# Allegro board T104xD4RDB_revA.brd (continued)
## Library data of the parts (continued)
C892 = CAP: signal model: DEFAULT_CAPACITOR_22.000000pF_2_1
C943 C966 = CAP: signal model: DEFAULT_CAPACITOR_560.000000pF_2_1
C967 = CAP: signal model: DEFAULT_CAPACITOR_620.000000pF_2_1
C991 = CAP: signal model: DEFAULT_CAPACITOR_680.000000pF_2_1
C1043 = CAP_E: signal model: DEFAULT_CAPACITOR_3.3e+08pF_2_1
C1138 = CAP
D1 D4-D6 = LED
D2 D3 = DIODE
D7 = DIODE_SCHOTTKY
F1-F5 = PTC
FB1-FB18 FB20-FB26 FB37-FB46 = BEAD
J1 = DDR4_DIMM
J2 = CONN_1X3
J3 = SD_CONN
J4 = CONN_2X8
J5 = USB_A_2
J6-J8 = JMP2
J9 = DSD9M
J10 = BAT_SOCKET
J11 = CONN_2X20
J12 = HDMI_CONN
J13 = FPC_20PIN
J14 J15 J18 J38 J39 = CONN_1X2
J16 J17 J32-J36 = CONN_3PIN
J19 = RJ45_LED_2X1
J20 J40 J41 = RJ45_LED
J21 = RJ45_LED_8
J26 = PCIE_X1
J27 J28 = MINIPCIE_CONN
J29 = SATA_CONN
J30 = CONN_2X35
J31 = CONN_2X5
J37 = ATX_PWR_CONN_20PIN
J42 = CONN_1X5
L1 L2 L19-L22 = IND_CM
L3 = IND: signal model: DEFAULT_INDUCTOR_2200nH_2_1
L4 L13 L15 = IND_IRON: signal model: DEFAULT_INDUCTOR_2200nH_2_1
L5 L12 L17 L18 = IND_IRON: signal model: DEFAULT_INDUCTOR_4700nH_2_1
L6 = IND_IRON: signal model: DEFAULT_INDUCTOR_220000nH_2_1
L7 = IND_IRON: signal model: DEFAULT_INDUCTOR_100000nH_2_1
L9 = IND_IRON: signal model: DEFAULT_INDUCTOR_215.000000nH_2_1
L10 L11 = IND_IRON: signal model: DEFAULT_INDUCTOR_3300nH_2_1
M2-M5 Z17 Z18 = MH
Q2-Q6 Q8 Q12-Q14 Q16-Q22 Q24-Q26 Q28 Q31 = NMOS
Q7 Q9-Q11 Q15 Q30 = NMOS_SO8FL
Q23 = PMOS_SO8
Q27 = PMOS
Q29 = TRANS_NPN
R1 = RES: tolerance: 1%; signal model: DEFAULT_RESISTOR_162.000000OHM_2_1
R2 R161 R503 R505 R509 R513 R516 R636 R640 = RES: tolerance: 1%; signal model: DEFAULT_RESISTOR_1000.000000OHM_2_1
R3 = RES: tolerance: 5%; signal model: DEFAULT_RESISTOR_162.000000OHM_2_1
R4-R7 R9-R11 R13 R17 R19 R21 R23 R25 R27 R29 R31 R33-R47 R53-R57 R69-R75 R78-R82 R85-R99 R101 R102 R123 R124 R132 R135-R137 R142-R144 R147 R148 R185 R204 R228-R235 R252 R259 R260 R262-R264 R269 R270 R272 R273 R276-R279 R282 R293-R297 R299-R301 R304-R306 R310 R311 R314-R321 R325 R330 R379-R385 R387-R393 R396-R399 R442 R443 R454 R496 R500 R501 R570 R698 R705 R706 R727-R729 R731 R732 R735-R738 R740 R749-R751 R753 R754 R757-R760 R763 = RES: tolerance: 5%; signal model: DEFAULT_RESISTOR_4700OHM_2_1
R8 R596 = RES: tolerance: 5%; signal model: DEFAULT_RESISTOR_20000OHM_2_1
R12 R59 R100 R108 R115-R122 R125-R130 R468 R486 R490 R549 R553 R555 R631 R694 = RES: tolerance: 5%; signal model: DEFAULT_RESISTOR_10.000000OHM_2_1
R14-R16 R18 R20 R22 R24 R26 R28 R30 R32 R58 R209 R211 R214-R217 R238 R239 R242-R246 R254 R255 R283 R448 R449 R492 R495 R511 = RES: tolerance: 5%; signal model: DEFAULT_RESISTOR_33.000000OHM_2_1
R48 R83 R84 R138 R162 R174 R176 R302 R323 R488 R494 R507 R518 R533 R540 R568 R652-R654 R656 R661 R665 R666 R670 R672 R673 R677 R681-R683 R687 R692 R695 R696 R718 R719 R722 = RES: tolerance: 5%; signal model: DEFAULT_RESISTOR_1000.000000OHM_2_1
R49-R52 R61 R151 R157 R170 R180 R182-R184 R190 R193 R221 R222 R226 R250 R251 R281 R312 R329 R489 R514 R515 R522 R525 R532 R552 R554 R572 R579 R588 R589 R607 R608 R625 R657 R659 R675 R676 R686 R688 R689 R700 R710-R717 R739 R741 R745 R761 R762 R767-R775 = RES: tolerance: 5%; signal model: DEFAULT_RESISTOR_0.001OHM_2_1
R60 R62-R68 R106 R107 R109-R112 R149 R150 R155 R156 R171 R456-R458 R462 R497 R498 R504 R506 R508 R539 R583 R585 R587 R601 R604-R606 R615 R618 R623 R642 R645 R648 R650 R658 R660 R662-R664 R667 R669 R671 R678 R679 R684 R685 R690 R691 R693 R703 R704 R721 R723 = RES: tolerance: 5%; signal model: DEFAULT_RESISTOR_10000OHM_2_1
R103 R133 R186 R187 R218 R219 R247 R248 R274 R275 R289 R290 R339 R341 R342 R352-R354 R363-R366 R375-R378 R394 R395 R470-R472 R699 R702 R733 R734 R755 R756 = RES: tolerance: 5%; signal model: DEFAULT_RESISTOR_510.000000OHM_2_1
R104 R105 R140 = RES: tolerance: 5%; signal model: DEFAULT_RESISTOR_698.000000OHM_2_1
R113 R114 R158 R159 R502 R558 R564 R577 R593 R599 R600 R602 R603 R613 R619 R627 R646 R651 = RES: tolerance: 1%; signal model: DEFAULT_RESISTOR_10000OHM_2_1
R131 = RES: tolerance: 5%; signal model: DEFAULT_RESISTOR_1500OHM_2_1
R134 = RES: tolerance: 5%; signal model: DEFAULT_RESISTOR_270.000000OHM_2_1
R139 = RES: tolerance: 5%; signal model: DEFAULT_RESISTOR_200.000000OHM_2_1
R145 = RES: tolerance: 1%; signal model: DEFAULT_RESISTOR_200.000000OHM_2_1
R146 = RES: tolerance: 1%; signal model: DEFAULT_RESISTOR_698.000000OHM_2_1
R152 R153 R641 R697 = RES: tolerance: 5%; signal model: DEFAULT_RESISTOR_100000OHM_2_1
R154 = RES: tolerance: 1%; signal model: DEFAULT_RESISTOR_51100OHM_2_1
R160 R167-R169 R520 R521 R536 R537 R701 = RES: tolerance: 1%; signal model: DEFAULT_RESISTOR_0.001OHM_2_1
R163 R164 = RES: tolerance: 5%; signal model: DEFAULT_RESISTOR_51100OHM_2_1
R165 = RES: tolerance: 5%; signal model: DEFAULT_RESISTOR_18200OHM_2_1
R166 = RES: tolerance: 1%; signal model: DEFAULT_RESISTOR_18200OHM_2_1
R172 R173 R519 R523 R524 R528 R538 = RES: tolerance: 5%; signal model: DEFAULT_RESISTOR_49.900000OHM_2_1
R175 R213 R517 = RES: tolerance: 1%; signal model: DEFAULT_RESISTOR_33.000000OHM_2_1
R177 R179 = RES: tolerance: 5%; signal model: DEFAULT_RESISTOR_330.000000OHM_2_1
R178 = RES: tolerance: 1%; signal model: DEFAULT_RESISTOR_330.000000OHM_2_1
R181 R188 R191 R194 R195 = RES: tolerance: 5%; signal model: DEFAULT_RESISTOR_5.100000OHM_2_1
R189 R192 = RES: tolerance: 5%; signal model: DEFAULT_RESISTOR_0.33OHM_2_1
R196-R203 R205 R206 R220 R249 R280 R292 R313 R386 R455 R551 R556 R655 R668 R674 R680 R707 R720 = RES: tolerance: 5%; signal model: DEFAULT_RESISTOR_100.000000OHM_2_1
R207 R208 R210 R236 R237 R240 R241 R265-R267 R271 R307-R309 R331 R333-R337 R344-R348 R350 R355-R362 R367-R374 R724-R726 R730 R746-R748 R752 = RES: tolerance: 5%; signal model: DEFAULT_RESISTOR_75.000000OHM_2_1
R212 R338 R349 R595 = RES: tolerance: 1%; signal model: DEFAULT_RESISTOR_75.000000OHM_2_1
R223 R225 = RES: tolerance: 5%; signal model: DEFAULT_RESISTOR_49900OHM_2_1
R224 R253 R284 R326 R742 R764 = RES: tolerance: 5%; signal model: DEFAULT_RESISTOR_15.000000OHM_2_1
R227 R256 R285 = RES: tolerance: 5%; signal model: DEFAULT_RESISTOR_2490OHM_2_1
R258 = RES: signal model: DEFAULT_RESISTOR_4700OHM_2_1
R268 R499 R574 = RES: tolerance: 1%; signal model: DEFAULT_RESISTOR_4700OHM_2_1
R286 = RES: tolerance: 5%; signal model: DEFAULT_RESISTOR_12100OHM_2_1
R288 = RES: signal model: DEFAULT_RESISTOR_33.000000OHM_2_1
R298 R327 R609 R743 R765 = RES: tolerance: 1%; signal model: DEFAULT_RESISTOR_2490OHM_2_1
R303 R324 = RES: tolerance: 5%; signal model: DEFAULT_RESISTOR_2000OHM_2_1
R328 R744 R766 = RES: tolerance: 1%; signal model: DEFAULT_RESISTOR_12100OHM_2_1
R340 R351 = RES: tolerance: 1%; signal model: DEFAULT_RESISTOR_510.000000OHM_2_1
R444 R452 R459 R461 = RES: tolerance: 5%; signal model: DEFAULT_RESISTOR_3010OHM_2_1
R445-R447 R450 R453 = RES: tolerance: 5%; signal model: DEFAULT_RESISTOR_51.000000OHM_2_1
R451 R464 R465 R480 R481 = RES: tolerance: 5%; signal model: DEFAULT_RESISTOR_200000OHM_2_1
R460 R463 R473-R479 = RES: tolerance: 5%; signal model: DEFAULT_RESISTOR_402000OHM_2_1
R466 R467 = RES: tolerance: 5%; signal model: DEFAULT_RESISTOR_47500OHM_2_1
R469 = RES: tolerance: 5%; signal model: DEFAULT_RESISTOR_75000OHM_2_1
R482-R485 = RES: tolerance: 5%; signal model: DEFAULT_RESISTOR_1800OHM_2_1
R487 R493 = RES: tolerance: 5%; signal model: DEFAULT_RESISTOR_13000OHM_2_1
R491 = RES: tolerance: 5%; signal model: DEFAULT_RESISTOR_0.02OHM_2_1
R512 R527 R535 = RES: tolerance: 1%; signal model: DEFAULT_RESISTOR_49.900000OHM_2_1
R534 = RES_PWR: signal model: DEFAULT_RESISTOR_49.900000OHM_2_1
R541-R545 R548 R708 R709 = RES: tolerance: 5%; signal model: DEFAULT_RESISTOR_150.000000OHM_2_1
R546 R547 = RES: tolerance: 1%; signal model: DEFAULT_RESISTOR_150.000000OHM_2_1
R550 = RES: tolerance: 1%; signal model: DEFAULT_RESISTOR_10.000000OHM_2_1
R565 R581 R590 = RES: tolerance: 5%; signal model: DEFAULT_RESISTOR_301.000000OHM_2_1
R566 R582 R591 = RES: tolerance: 1%; signal model: DEFAULT_RESISTOR_301.000000OHM_2_1
R567 R592 = RES: tolerance: 1%; signal model: DEFAULT_RESISTOR_1.000000OHM_2_1
R575 R610 = RES: tolerance: 1%; signal model: DEFAULT_RESISTOR_1780OHM_2_1
R576 R580 = RES: tolerance: 1%; signal model: DEFAULT_RESISTOR_2870OHM_2_1
R578 = RES: tolerance: 1%; signal model: DEFAULT_RESISTOR_3400OHM_2_1
R584 = RES: tolerance: 1%; signal model: DEFAULT_RESISTOR_2430OHM_2_1
R586 = RES: tolerance: 1%; signal model: DEFAULT_RESISTOR_3570OHM_2_1
R594 = RES: tolerance: 1%; signal model: DEFAULT_RESISTOR_7500OHM_2_1
R597 = RES: tolerance: 1%; signal model: DEFAULT_RESISTOR_49900OHM_2_1
R598 = RES: tolerance: 5%; signal model: DEFAULT_RESISTOR_46400OHM_2_1
R611 = RES: tolerance: 1%; signal model: DEFAULT_RESISTOR_124000OHM_2_1
R616 = RES: tolerance: 1%; signal model: DEFAULT_RESISTOR_1650OHM_2_1
R643 R649 = RES: tolerance: 1%; signal model: DEFAULT_RESISTOR_4320OHM_2_1
R644 = RES: tolerance: 1%; signal model: DEFAULT_RESISTOR_39200OHM_2_1
R647 = RES: tolerance: 1%; signal model: DEFAULT_RESISTOR_36500OHM_2_1
SW1-SW3 = SWITCH_DIP_8
SW4 SW5 = SWITCH_2P2
T1-T3 T12 T13 = H5007
T4-T11 = GST5009LF
TP1-TP19 = TP
U1 = T1040
U2 = 74LVC16373
U3 = FLASH-NOR-64Mx16
U4 = FLASH-NAND-BGA
U5-U7 = 74LVC1G86
U8 = FLASH-SERIAL-SO16
U9 = FLASH-SERIAL-SON
U10 U11 = RClamp0524J
U12 = PCA9546A
U13 = FXLP34P5X
U16-U18 = PI3PCIE3212
U19 = MAX1558H
U20 = SRV05-4
U21-U24 U26-U28 = 74CBTLV3253
U25 = 74LVC125
U29 U30 = MAX3232
U31 = DS1339U
U32 = EEPROM-I2C
U33 = LCDA15C-8
U34 = ADT7461
U35 = CH7301C
U36 = CM2020
U37 = DS90C387R
U38 = NKE0505SC_SIP_4P
U39 = 74CBTLV3257
U40 = ISO1176_SO16
U41 U78 = 74LVC1G14
U42 U45 = RTL8211E-VB
U48 U82 U83 = RTL8211DN
U51 U52 = VSC8514
U57 = EPM570F256
U58 = ICS843004-01
U60 U64-U69 = IR3475
U61 = 74CBTLV1G125
U62 = INA220
U72 = TPS51200
U73 U75 = MIC47100-MSOP8
U74 = TPS73701_SOT223
U76 = MAX811S
U77 = 74LVC2G74
U79 = IDT9FGV0641
U80 U81 = 74LVC1G66
X1-X4 = OSC
Y1 = CRYSTAL_32K
Y2-Y4 Y7-Y10 = CRYSTAL_4PIN
Z1-Z8 = FIDUCIAL
Z9-Z16 = MH_M8

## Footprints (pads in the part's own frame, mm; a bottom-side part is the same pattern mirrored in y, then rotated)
0201
  rect 0.32x0.3 smd: 1(-0.27,0) 2(0.27,0)
0402
  rect 0.55x0.5 smd: 1(-0.483,0) 2(0.483,0)
0402O
  custom 0.138x0.138 smd: 1(-0.5,0) 2(0.5,0)
0603
  rect 0.85x0.85 smd: 1(-0.762,0) 2(0.762,0)
0805
  rect 0.95x1.3 smd: 1(-0.965,0) 2(0.965,0)
0806
  rect 0.95x1.7 smd: 1(-0.965,0) 2(0.965,0)
1206
  rect 1.25x1.6 smd: 1(-1.524,0) 2(1.524,0)
7343
  rect 2.4x2.9 smd: 1(-3.05,0) 2(3.05,0)
BGA_P080_780
  round 0.35 smd: A2(-10,10.8) A3(-9.2,10.8) A4(-8.4,10.8) A5(-7.6,10.8) A6(-6.8,10.8) A7(-6,10.8) A8(-5.2,10.8) A9(-4.4,10.8) A10(-3.6,10.8) A11(-2.8,10.8) A12(-2,10.8) A13(-1.2,10.8) A14(-0.4,10.8) A15(0.4,10.8) A16(1.2,10.8) A17(2,10.8) A18(2.8,10.8) A19(3.6,10.8) A20(4.4,10.8) A21(5.2,10.8) A22(6,10.8) A23(6.8,10.8) A24(7.6,10.8) A25(8.4,10.8) A26(9.2,10.8) A27(10,10.8) AA1(-10.8,-5.2) AA2(-10,-5.2) AA3(-9.2,-5.2) AA4(-8.4,-5.2) AA5(-7.6,-5.2) AA6(-6.8,-5.2) AA7(-6,-5.2) AA8(-5.2,-5.2) AA9(-4.4,-5.2) AA10(-3.6,-5.2) AA11(-2.8,-5.2) AA12(-2,-5.2) AA13(-1.2,-5.2) AA14(-0.4,-5.2) AA15(0.4,-5.2) AA16(1.2,-5.2) AA17(2,-5.2) AA18(2.8,-5.2) AA19(3.6,-5.2) AA20(4.4,-5.2) AA21(5.2,-5.2) AA22(6,-5.2) AA23(6.8,-5.2) AA24(7.6,-5.2) AA25(8.4,-5.2) AA26(9.2,-5.2) AA27(10,-5.2) AA28(10.8,-5.2) AB1(-10.8,-6) AB2(-10,-6) AB3(-9.2,-6) AB4(-8.4,-6) AB5(-7.6,-6) AB6(-6.8,-6) AB7(-6,-6) AB8(-5.2,-6) AB9(-4.4,-6) AB10(-3.6,-6) AB11(-2.8,-6) AB12(-2,-6) AB13(-1.2,-6) AB14(-0.4,-6) AB15(0.4,-6) AB16(1.2,-6) AB17(2,-6) AB18(2.8,-6) AB19(3.6,-6) AB20(4.4,-6) AB21(5.2,-6) AB22(6,-6) AB23(6.8,-6) AB24(7.6,-6) AB25(8.4,-6) AB26(9.2,-6) AB27(10,-6) AB28(10.8,-6) AC1(-10.8,-6.8) AC2(-10,-6.8) AC3(-9.2,-6.8) AC4(-8.4,-6.8) AC5(-7.6,-6.8) AC6(-6.8,-6.8) AC7(-6,-6.8) AC8(-5.2,-6.8) AC9(-4.4,-6.8) AC10(-3.6,-6.8) AC11(-2.8,-6.8) AC12(-2,-6.8) AC13(-1.2,-6.8) AC14(-0.4,-6.8) AC15(0.4,-6.8) AC16(1.2,-6.8) AC17(2,-6.8) AC18(2.8,-6.8) AC19(3.6,-6.8) AC20(4.4,-6.8) AC21(5.2,-6.8) AC22(6,-6.8) AC23(6.8,-6.8) AC24(7.6,-6.8) AC25(8.4,-6.8) AC26(9.2,-6.8) AC27(10,-6.8) AC28(10.8,-6.8) AD1(-10.8,-7.6) AD2(-10,-7.6) AD3(-9.2,-7.6) AD4(-8.4,-7.6) AD5(-7.6,-7.6) AD6(-6.8,-7.6) AD7(-6,-7.6) AD8(-5.2,-7.6) AD9(-4.4,-7.6) AD10(-3.6,-7.6) AD11(-2.8,-7.6) AD12(-2,-7.6) AD13(-1.2,-7.6) AD14(-0.4,-7.6) AD15(0.4,-7.6) AD16(1.2,-7.6) AD17(2,-7.6) AD18(2.8,-7.6) AD19(3.6,-7.6) AD20(4.4,-7.6) AD21(5.2,-7.6) AD22(6,-7.6) AD23(6.8,-7.6) AD24(7.6,-7.6) AD25(8.4,-7.6) AD26(9.2,-7.6) AD27(10,-7.6) AD28(10.8,-7.6) AE1(-10.8,-8.4) AE2(-10,-8.4) AE3(-9.2,-8.4) AE4(-8.4,-8.4) AE5(-7.6,-8.4) AE6(-6.8,-8.4) AE7(-6,-8.4) AE8(-5.2,-8.4) AE9(-4.4,-8.4) AE10(-3.6,-8.4) AE11(-2.8,-8.4) AE12(-2,-8.4) AE13(-1.2,-8.4) AE14(-0.4,-8.4) AE15(0.4,-8.4) AE16(1.2,-8.4) AE17(2,-8.4) AE18(2.8,-8.4) AE19(3.6,-8.4) AE20(4.4,-8.4) AE21(5.2,-8.4) AE22(6,-8.4) AE23(6.8,-8.4) AE24(7.6,-8.4) AE25(8.4,-8.4) AE26(9.2,-8.4) AE27(10,-8.4) AE28(10.8,-8.4) AF1(-10.8,-9.2) AF2(-10,-9.2) AF3(-9.2,-9.2) AF4(-8.4,-9.2) AF5(-7.6,-9.2) AF6(-6.8,-9.2) AF7(-6,-9.2) AF8(-5.2,-9.2) AF9(-4.4,-9.2) AF10(-3.6,-9.2) AF11(-2.8,-9.2) AF12(-2,-9.2) AF13(-1.2,-9.2) AF14(-0.4,-9.2) AF15(0.4,-9.2) AF16(1.2,-9.2) AF17(2,-9.2) AF18(2.8,-9.2) AF19(3.6,-9.2) AF20(4.4,-9.2) AF21(5.2,-9.2) AF22(6,-9.2) AF23(6.8,-9.2) AF24(7.6,-9.2) AF25(8.4,-9.2) AF26(9.2,-9.2) AF27(10,-9.2) AF28(10.8,-9.2) AG1(-10.8,-10) AG2(-10,-10) AG3(-9.2,-10) AG4(-8.4,-10) AG5(-7.6,-10) AG6(-6.8,-10) AG7(-6,-10) AG8(-5.2,-10) AG9(-4.4,-10) AG10(-3.6,-10) AG11(-2.8,-10) AG12(-2,-10) AG13(-1.2,-10) AG14(-0.4,-10) AG15(0.4,-10) AG16(1.2,-10) AG17(2,-10) AG18(2.8,-10) AG19(3.6,-10) AG20(4.4,-10) AG21(5.2,-10) AG22(6,-10) AG23(6.8,-10) AG24(7.6,-10) AG25(8.4,-10) AG26(9.2,-10) AG27(10,-10) AG28(10.8,-10) AH2(-10,-10.8) AH3(-9.2,-10.8) AH4(-8.4,-10.8) AH5(-7.6,-10.8) AH6(-6.8,-10.8) AH7(-6,-10.8) AH8(-5.2,-10.8) AH9(-4.4,-10.8) AH10(-3.6,-10.8) AH11(-2.8,-10.8) AH12(-2,-10.8) AH13(-1.2,-10.8) AH14(-0.4,-10.8) AH15(0.4,-10.8) AH16(1.2,-10.8) AH17(2,-10.8) AH18(2.8,-10.8) AH19(3.6,-10.8) AH20(4.4,-10.8) AH21(5.2,-10.8) AH22(6,-10.8) AH23(6.8,-10.8) AH24(7.6,-10.8) AH25(8.4,-10.8) AH26(9.2,-10.8) AH27(10,-10.8) B1(-10.8,10) B2(-10,10) B3(-9.2,10) B4(-8.4,10) B5(-7.6,10) B6(-6.8,10) B7(-6,10) B8(-5.2,10) B9(-4.4,10) B10(-3.6,10) B11(-2.8,10) B12(-2,10) B13(-1.2,10) B14(-0.4,10) B15(0.4,10) B16(1.2,10) B17(2,10) B18(2.8,10) B19(3.6,10) B20(4.4,10) B21(5.2,10) B22(6,10) B23(6.8,10) B24(7.6,10) B25(8.4,10) B26(9.2,10) B27(10,10) B28(10.8,10) C1(-10.8,9.2) C2(-10,9.2) C3(-9.2,9.2) C4(-8.4,9.2) C5(-7.6,9.2) C6(-6.8,9.2) C7(-6,9.2) C8(-5.2,9.2) C9(-4.4,9.2) C10(-3.6,9.2) C11(-2.8,9.2) C12(-2,9.2) C13(-1.2,9.2) C14(-0.4,9.2) C15(0.4,9.2) C16(1.2,9.2) C17(2,9.2) C18(2.8,9.2) C19(3.6,9.2) C20(4.4,9.2) C21(5.2,9.2) C22(6,9.2) C23(6.8,9.2) C24(7.6,9.2) C25(8.4,9.2) C26(9.2,9.2) C27(10,9.2) C28(10.8,9.2) D1(-10.8,8.4) D2(-10,8.4) D3(-9.2,8.4) D4(-8.4,8.4) D5(-7.6,8.4) D6(-6.8,8.4) D7(-6,8.4) D8(-5.2,8.4) D9(-4.4,8.4) D10(-3.6,8.4) D11(-2.8,8.4) D12(-2,8.4) D13(-1.2,8.4) D14(-0.4,8.4) D15(0.4,8.4) D16(1.2,8.4) D17(2,8.4) D18(2.8,8.4) D19(3.6,8.4) D20(4.4,8.4) D21(5.2,8.4) D22(6,8.4) D23(6.8,8.4) D24(7.6,8.4) D25(8.4,8.4) D26(9.2,8.4) D27(10,8.4) D28(10.8,8.4) E1(-10.8,7.6) E2(-10,7.6) E3(-9.2,7.6) E4(-8.4,7.6) E5(-7.6,7.6) E6(-6.8,7.6) E7(-6,7.6) E8(-5.2,7.6) E9(-4.4,7.6) E10(-3.6,7.6) E11(-2.8,7.6) E12(-2,7.6) E13(-1.2,7.6) E14(-0.4,7.6) E15(0.4,7.6) E16(1.2,7.6) E17(2,7.6) E18(2.8,7.6) E19(3.6,7.6) E20(4.4,7.6) E21(5.2,7.6) E22(6,7.6) E23(6.8,7.6) E24(7.6,7.6) E25(8.4,7.6) E26(9.2,7.6) E27(10,7.6) E28(10.8,7.6) F1(-10.8,6.8) F2(-10,6.8) F3(-9.2,6.8) F4(-8.4,6.8) F5(-7.6,6.8) F6(-6.8,6.8) F7(-6,6.8) F8(-5.2,6.8) F9(-4.4,6.8) F10(-3.6,6.8) F11(-2.8,6.8) F12(-2,6.8) F13(-1.2,6.8) F14(-0.4,6.8) F15(0.4,6.8) F16(1.2,6.8) F17(2,6.8) F18(2.8,6.8) F19(3.6,6.8) F20(4.4,6.8) F21(5.2,6.8) F22(6,6.8) F23(6.8,6.8) F24(7.6,6.8) F25(8.4,6.8) F26(9.2,6.8) F27(10,6.8) F28(10.8,6.8) G1(-10.8,6) G2(-10,6) G3(-9.2,6) G4(-8.4,6) G5(-7.6,6) G6(-6.8,6) G7(-6,6) G8(-5.2,6) G9(-4.4,6) G10(-3.6,6) G11(-2.8,6) G12(-2,6) G13(-1.2,6) G14(-0.4,6) G15(0.4,6) G16(1.2,6) G17(2,6) G18(2.8,6) G19(3.6,6) G20(4.4,6) G21(5.2,6) G22(6,6) G23(6.8,6) G24(7.6,6) G25(8.4,6) G26(9.2,6) G27(10,6) G28(10.8,6) H1(-10.8,5.2) H2(-10,5.2) H3(-9.2,5.2) H4(-8.4,5.2) H5(-7.6,5.2) H6(-6.8,5.2) H7(-6,5.2) H8(-5.2,5.2) H9(-4.4,5.2) H10(-3.6,5.2) H11(-2.8,5.2) H12(-2,5.2) H13(-1.2,5.2) H14(-0.4,5.2) H15(0.4,5.2) H16(1.2,5.2) H17(2,5.2) H18(2.8,5.2) H19(3.6,5.2) H20(4.4,5.2) H21(5.2,5.2) H22(6,5.2) H23(6.8,5.2) H24(7.6,5.2) H25(8.4,5.2) H26(9.2,5.2) H27(10,5.2) H28(10.8,5.2) J1(-10.8,4.4) J2(-10,4.4) J3(-9.2,4.4) J4(-8.4,4.4) J5(-7.6,4.4) J6(-6.8,4.4) J7(-6,4.4) J8(-5.2,4.4) J9(-4.4,4.4) J10(-3.6,4.4) J11(-2.8,4.4) J12(-2,4.4) J13(-1.2,4.4) J14(-0.4,4.4) J15(0.4,4.4) J16(1.2,4.4) J17(2,4.4) J18(2.8,4.4) J19(3.6,4.4) J20(4.4,4.4) J21(5.2,4.4) J22(6,4.4) J23(6.8,4.4) J24(7.6,4.4) J25(8.4,4.4) J26(9.2,4.4) J27(10,4.4) J28(10.8,4.4) K1(-10.8,3.6) K2(-10,3.6) K3(-9.2,3.6) K4(-8.4,3.6) K5(-7.6,3.6) K6(-6.8,3.6) K7(-6,3.6) K8(-5.2,3.6) K9(-4.4,3.6) K10(-3.6,3.6) K11(-2.8,3.6) K12(-2,3.6) K13(-1.2,3.6) K14(-0.4,3.6) K15(0.4,3.6) K16(1.2,3.6) K17(2,3.6) K18(2.8,3.6) K19(3.6,3.6) K20(4.4,3.6) K21(5.2,3.6) K22(6,3.6) K23(6.8,3.6) K24(7.6,3.6) K25(8.4,3.6) K26(9.2,3.6) K27(10,3.6) K28(10.8,3.6) L1(-10.8,2.8) L2(-10,2.8) L3(-9.2,2.8) L4(-8.4,2.8) L5(-7.6,2.8) L6(-6.8,2.8) L7(-6,2.8) L8(-5.2,2.8) L9(-4.4,2.8) L10(-3.6,2.8) L11(-2.8,2.8) L12(-2,2.8) L13(-1.2,2.8) L14(-0.4,2.8) L15(0.4,2.8) L16(1.2,2.8) L17(2,2.8) L18(2.8,2.8) L19(3.6,2.8) L20(4.4,2.8) L21(5.2,2.8) L22(6,2.8) L23(6.8,2.8) L24(7.6,2.8) L25(8.4,2.8) L26(9.2,2.8) L27(10,2.8) L28(10.8,2.8) M1(-10.8,2) M2(-10,2) M3(-9.2,2) M4(-8.4,2) M5(-7.6,2) M6(-6.8,2) M7(-6,2) M8(-5.2,2) M9(-4.4,2) M10(-3.6,2) M11(-2.8,2) M12(-2,2) M13(-1.2,2) M14(-0.4,2) M15(0.4,2) M16(1.2,2) M17(2,2) M18(2.8,2) M19(3.6,2) M20(4.4,2) M21(5.2,2) M22(6,2) M23(6.8,2) M24(7.6,2) M25(8.4,2) M26(9.2,2) M27(10,2) M28(10.8,2) N1(-10.8,1.2) N2(-10,1.2) N3(-9.2,1.2) N4(-8.4,1.2) N5(-7.6,1.2) N6(-6.8,1.2) N7(-6,1.2) N8(-5.2,1.2) N9(-4.4,1.2) N10(-3.6,1.2) N11(-2.8,1.2) N12(-2,1.2) N13(-1.2,1.2) N14(-0.4,1.2) N15(0.4,1.2) N16(1.2,1.2) N17(2,1.2) N18(2.8,1.2) N19(3.6,1.2) N20(4.4,1.2) N21(5.2,1.2) N22(6,1.2) N23(6.8,1.2) N24(7.6,1.2) N25(8.4,1.2) N26(9.2,1.2) N27(10,1.2) N28(10.8,1.2) P1(-10.8,0.4) P2(-10,0.4) P3(-9.2,0.4) P4(-8.4,0.4) P5(-7.6,0.4) P6(-6.8,0.4) P7(-6,0.4) P8(-5.2,0.4) P9(-4.4,0.4) P10(-3.6,0.4) P11(-2.8,0.4) P12(-2,0.4) P13(-1.2,0.4) P14(-0.4,0.4) P15(0.4,0.4) P16(1.2,0.4) P17(2,0.4) P18(2.8,0.4) P19(3.6,0.4) P20(4.4,0.4) P21(5.2,0.4) P22(6,0.4) P23(6.8,0.4) P24(7.6,0.4) P25(8.4,0.4) P26(9.2,0.4) P27(10,0.4) P28(10.8,0.4) R1(-10.8,-0.4) R2(-10,-0.4) R3(-9.2,-0.4) R4(-8.4,-0.4) R5(-7.6,-0.4) R6(-6.8,-0.4) R7(-6,-0.4) R8(-5.2,-0.4) R9(-4.4,-0.4) R10(-3.6,-0.4) R11(-2.8,-0.4) R12(-2,-0.4) R13(-1.2,-0.4) R14(-0.4,-0.4) R15(0.4,-0.4) R16(1.2,-0.4) R17(2,-0.4) R18(2.8,-0.4) R19(3.6,-0.4) R20(4.4,-0.4) R21(5.2,-0.4) R22(6,-0.4) R23(6.8,-0.4) R24(7.6,-0.4) R25(8.4,-0.4) R26(9.2,-0.4) R27(10,-0.4) R28(10.8,-0.4) T1(-10.8,-1.2) T2(-10,-1.2) T3(-9.2,-1.2) T4(-8.4,-1.2) T5(-7.6,-1.2) T6(-6.8,-1.2) T7(-6,-1.2) T8(-5.2,-1.2) T9(-4.4,-1.2) T10(-3.6,-1.2) T11(-2.8,-1.2) T12(-2,-1.2) T13(-1.2,-1.2) T14(-0.4,-1.2) T15(0.4,-1.2) T16(1.2,-1.2) T17(2,-1.2) T18(2.8,-1.2) T19(3.6,-1.2) T20(4.4,-1.2) T21(5.2,-1.2) T22(6,-1.2) T23(6.8,-1.2) T24(7.6,-1.2) T25(8.4,-1.2) T26(9.2,-1.2) T27(10,-1.2) T28(10.8,-1.2) U1(-10.8,-2) U2(-10,-2) U3(-9.2,-2) U4(-8.4,-2) U5(-7.6,-2) U6(-6.8,-2) U7(-6,-2) U8(-5.2,-2) U9(-4.4,-2) U10(-3.6,-2) U11(-2.8,-2) U12(-2,-2) U13(-1.2,-2) U14(-0.4,-2) U15(0.4,-2) U16(1.2,-2) U17(2,-2) U18(2.8,-2) U19(3.6,-2) U20(4.4,-2) U21(5.2,-2) U22(6,-2) U23(6.8,-2) U24(7.6,-2) U25(8.4,-2) U26(9.2,-2) U27(10,-2) U28(10.8,-2) V1(-10.8,-2.8) V2(-10,-2.8) V3(-9.2,-2.8) V4(-8.4,-2.8) V5(-7.6,-2.8) V6(-6.8,-2.8) V7(-6,-2.8) V8(-5.2,-2.8) V9(-4.4,-2.8) V10(-3.6,-2.8) V11(-2.8,-2.8) V12(-2,-2.8) V13(-1.2,-2.8) V14(-0.4,-2.8) V15(0.4,-2.8) V16(1.2,-2.8) V17(2,-2.8) V18(2.8,-2.8) V19(3.6,-2.8) V20(4.4,-2.8) V21(5.2,-2.8) V22(6,-2.8) V23(6.8,-2.8) V24(7.6,-2.8) V25(8.4,-2.8) V26(9.2,-2.8) V27(10,-2.8) V28(10.8,-2.8) W1(-10.8,-3.6) W2(-10,-3.6) W3(-9.2,-3.6) W4(-8.4,-3.6) W5(-7.6,-3.6) W6(-6.8,-3.6) W7(-6,-3.6) W8(-5.2,-3.6) W9(-4.4,-3.6) W10(-3.6,-3.6) W11(-2.8,-3.6) W12(-2,-3.6) W13(-1.2,-3.6) W14(-0.4,-3.6) W15(0.4,-3.6) W16(1.2,-3.6) W17(2,-3.6) W18(2.8,-3.6) W19(3.6,-3.6) W20(4.4,-3.6) W21(5.2,-3.6) W22(6,-3.6) W23(6.8,-3.6) W24(7.6,-3.6) W25(8.4,-3.6) W26(9.2,-3.6) W27(10,-3.6) W28(10.8,-3.6) Y1(-10.8,-4.4) Y2(-10,-4.4) Y3(-9.2,-4.4) Y4(-8.4,-4.4) Y5(-7.6,-4.4) Y6(-6.8,-4.4) Y7(-6,-4.4) Y8(-5.2,-4.4) Y9(-4.4,-4.4) Y10(-3.6,-4.4) Y11(-2.8,-4.4) Y12(-2,-4.4) Y13(-1.2,-4.4) Y14(-0.4,-4.4) Y15(0.4,-4.4) Y16(1.2,-4.4) Y17(2,-4.4) Y18(2.8,-4.4) Y19(3.6,-4.4) Y20(4.4,-4.4) Y21(5.2,-4.4) Y22(6,-4.4) Y23(6.8,-4.4) Y24(7.6,-4.4) Y25(8.4,-4.4) Y26(9.2,-4.4) Y27(10,-4.4) Y28(10.8,-4.4)
BGA_P080_NAND_63
  round 0.35 smd: A1(-3.6,4.4) A2(-2.8,4.4) A9(2.8,4.4) A10(3.6,4.4) B1(-3.6,3.6) B9(2.8,3.6) B10(3.6,3.6) C3(-2,2.8) C4(-1.2,2.8) C5(-0.4,2.8) C6(0.4,2.8) C7(1.2,2.8) C8(2,2.8) D3(-2,2) D4(-1.2,2) D5(-0.4,2) D6(0.4,2) D7(1.2,2) D8(2,2) E3(-2,1.2) E4(-1.2,1.2) E5(-0.4,1.2) E6(0.4,1.2) E7(1.2,1.2) E8(2,1.2) F3(-2,0.4) F4(-1.2,0.4) F5(-0.4,0.4) F6(0.4,0.4) F7(1.2,0.4) F8(2,0.4) G3(-2,-0.4) G4(-1.2,-0.4) G5(-0.4,-0.4) G6(0.4,-0.4) G7(1.2,-0.4) G8(2,-0.4) H3(-2,-1.2) H4(-1.2,-1.2) H5(-0.4,-1.2) H6(0.4,-1.2) H7(1.2,-1.2) H8(2,-1.2) J3(-2,-2) J4(-1.2,-2) J5(-0.4,-2) J6(0.4,-2) J7(1.2,-2) J8(2,-2) K3(-2,-2.8) K4(-1.2,-2.8) K5(-0.4,-2.8) K6(0.4,-2.8) K7(1.2,-2.8) K8(2,-2.8) L1(-3.6,-3.6) L2(-2.8,-3.6) L9(2.8,-3.6) L10(3.6,-3.6) M1(-3.6,-4.4) M2(-2.8,-4.4) M9(2.8,-4.4) M10(3.6,-4.4)
BGA_P100_256
  round 0.45 smd: A1(-7.5,7.5) A2(-6.5,7.5) A3(-5.5,7.5) A4(-4.5,7.5) A5(-3.5,7.5) A6(-2.5,7.5) A7(-1.5,7.5) A8(-0.5,7.5) A9(0.5,7.5) A10(1.5,7.5) A11(2.5,7.5) A12(3.5,7.5) A13(4.5,7.5) A14(5.5,7.5) A15(6.5,7.5) A16(7.5,7.5) B1(-7.5,6.5) B2(-6.5,6.5) B3(-5.5,6.5) B4(-4.5,6.5) B5(-3.5,6.5) B6(-2.5,6.5) B7(-1.5,6.5) B8(-0.5,6.5) B9(0.5,6.5) B10(1.5,6.5) B11(2.5,6.5) B12(3.5,6.5) B13(4.5,6.5) B14(5.5,6.5) B15(6.5,6.5) B16(7.5,6.5) C1(-7.5,5.5) C2(-6.5,5.5) C3(-5.5,5.5) C4(-4.5,5.5) C5(-3.5,5.5) C6(-2.5,5.5) C7(-1.5,5.5) C8(-0.5,5.5) C9(0.5,5.5) C10(1.5,5.5) C11(2.5,5.5) C12(3.5,5.5) C13(4.5,5.5) C14(5.5,5.5) C15(6.5,5.5) C16(7.5,5.5) D1(-7.5,4.5) D2(-6.5,4.5) D3(-5.5,4.5) D4(-4.5,4.5) D5(-3.5,4.5) D6(-2.5,4.5) D7(-1.5,4.5) D8(-0.5,4.5) D9(0.5,4.5) D10(1.5,4.5) D11(2.5,4.5) D12(3.5,4.5) D13(4.5,4.5) D14(5.5,4.5) D15(6.5,4.5) D16(7.5,4.5) E1(-7.5,3.5) E2(-6.5,3.5) E3(-5.5,3.5) E4(-4.5,3.5) E5(-3.5,3.5) E6(-2.5,3.5) E7(-1.5,3.5) E8(-0.5,3.5) E9(0.5,3.5) E10(1.5,3.5) E11(2.5,3.5) E12(3.5,3.5) E13(4.5,3.5) E14(5.5,3.5) E15(6.5,3.5) E16(7.5,3.5) F1(-7.5,2.5) F2(-6.5,2.5) F3(-5.5,2.5) F4(-4.5,2.5) F5(-3.5,2.5) F6(-2.5,2.5) F7(-1.5,2.5) F8(-0.5,2.5) F9(0.5,2.5) F10(1.5,2.5) F11(2.5,2.5) F12(3.5,2.5) F13(4.5,2.5) F14(5.5,2.5) F15(6.5,2.5) F16(7.5,2.5) G1(-7.5,1.5) G2(-6.5,1.5) G3(-5.5,1.5) G4(-4.5,1.5) G5(-3.5,1.5) G6(-2.5,1.5) G7(-1.5,1.5) G8(-0.5,1.5) G9(0.5,1.5) G10(1.5,1.5) G11(2.5,1.5) G12(3.5,1.5) G13(4.5,1.5) G14(5.5,1.5) G15(6.5,1.5) G16(7.5,1.5) H1(-7.5,0.5) H2(-6.5,0.5) H3(-5.5,0.5) H4(-4.5,0.5) H5(-3.5,0.5) H6(-2.5,0.5) H7(-1.5,0.5) H8(-0.5,0.5) H9(0.5,0.5) H10(1.5,0.5) H11(2.5,0.5) H12(3.5,0.5) H13(4.5,0.5) H14(5.5,0.5) H15(6.5,0.5) H16(7.5,0.5) J1(-7.5,-0.5) J2(-6.5,-0.5) J3(-5.5,-0.5) J4(-4.5,-0.5) J5(-3.5,-0.5) J6(-2.5,-0.5) J7(-1.5,-0.5) J8(-0.5,-0.5) J9(0.5,-0.5) J10(1.5,-0.5) J11(2.5,-0.5) J12(3.5,-0.5) J13(4.5,-0.5) J14(5.5,-0.5) J15(6.5,-0.5) J16(7.5,-0.5) K1(-7.5,-1.5) K2(-6.5,-1.5) K3(-5.5,-1.5) K4(-4.5,-1.5) K5(-3.5,-1.5) K6(-2.5,-1.5) K7(-1.5,-1.5) K8(-0.5,-1.5) K9(0.5,-1.5) K10(1.5,-1.5) K11(2.5,-1.5) K12(3.5,-1.5) K13(4.5,-1.5) K14(5.5,-1.5) K15(6.5,-1.5) K16(7.5,-1.5) L1(-7.5,-2.5) L2(-6.5,-2.5) L3(-5.5,-2.5) L4(-4.5,-2.5) L5(-3.5,-2.5) L6(-2.5,-2.5) L7(-1.5,-2.5) L8(-0.5,-2.5) L9(0.5,-2.5) L10(1.5,-2.5) L11(2.5,-2.5) L12(3.5,-2.5) L13(4.5,-2.5) L14(5.5,-2.5) L15(6.5,-2.5) L16(7.5,-2.5) M1(-7.5,-3.5) M2(-6.5,-3.5) M3(-5.5,-3.5) M4(-4.5,-3.5) M5(-3.5,-3.5) M6(-2.5,-3.5) M7(-1.5,-3.5) M8(-0.5,-3.5) M9(0.5,-3.5) M10(1.5,-3.5) M11(2.5,-3.5) M12(3.5,-3.5) M13(4.5,-3.5) M14(5.5,-3.5) M15(6.5,-3.5) M16(7.5,-3.5) N1(-7.5,-4.5) N2(-6.5,-4.5) N3(-5.5,-4.5) N4(-4.5,-4.5) N5(-3.5,-4.5) N6(-2.5,-4.5) N7(-1.5,-4.5) N8(-0.5,-4.5) N9(0.5,-4.5) N10(1.5,-4.5) N11(2.5,-4.5) N12(3.5,-4.5) N13(4.5,-4.5) N14(5.5,-4.5) N15(6.5,-4.5) N16(7.5,-4.5) P1(-7.5,-5.5) P2(-6.5,-5.5) P3(-5.5,-5.5) P4(-4.5,-5.5) P5(-3.5,-5.5) P6(-2.5,-5.5) P7(-1.5,-5.5) P8(-0.5,-5.5) P9(0.5,-5.5) P10(1.5,-5.5) P11(2.5,-5.5) P12(3.5,-5.5) P13(4.5,-5.5) P14(5.5,-5.5) P15(6.5,-5.5) P16(7.5,-5.5) R1(-7.5,-6.5) R2(-6.5,-6.5) R3(-5.5,-6.5) R4(-4.5,-6.5) R5(-3.5,-6.5) R6(-2.5,-6.5) R7(-1.5,-6.5) R8(-0.5,-6.5) R9(0.5,-6.5) R10(1.5,-6.5) R11(2.5,-6.5) R12(3.5,-6.5) R13(4.5,-6.5) R14(5.5,-6.5) R15(6.5,-6.5) R16(7.5,-6.5) T1(-7.5,-7.5) T2(-6.5,-7.5) T3(-5.5,-7.5) T4(-4.5,-7.5) T5(-3.5,-7.5) T6(-2.5,-7.5) T7(-1.5,-7.5) T8(-0.5,-7.5) T9(0.5,-7.5) T10(1.5,-7.5) T11(2.5,-7.5) T12(3.5,-7.5) T13(4.5,-7.5) T14(5.5,-7.5) T15(6.5,-7.5) T16(7.5,-7.5)
CAPE_B6D3
  rect 3.5x1.6 smd: 1(-2.8,0) 2(2.8,0)
CAPE_B8
  rect 4.15x1.9 smd: 1(-3.475,0) 2(3.475,0)
CON2X35_SKT_0P8_SM
  round 0.254 hole 1.448 unplated: (-15.4,1.5) (15.4,1.5)
  rect 0.508x1.092 smd: 1(-13.6,-2.255) 2(-13.6,2.255) 3(-12.8,-2.255) 4(-12.8,2.255) 5(-12,-2.255) 6(-12,2.255) 7(-11.2,-2.255) 8(-11.2,2.255) 9(-10.4,-2.255) 10(-10.4,2.255) 11(-9.6,-2.255) 12(-9.6,2.255) 13(-8.8,-2.255) 14(-8.8,2.255) 15(-8,-2.255) 16(-8,2.255) 17(-7.2,-2.255) 18(-7.2,2.255) 19(-6.4,-2.255) 20(-6.4,2.255) 21(-5.6,-2.255) 22(-5.6,2.255) 23(-4.8,-2.255) 24(-4.8,2.255) 25(-4,-2.255) 26(-4,2.255) 27(-3.2,-2.255) 28(-3.2,2.255) 29(-2.4,-2.255) 30(-2.4,2.255) 31(-1.6,-2.255) 32(-1.6,2.255) 33(-0.8,-2.255) 34(-0.8,2.255) 35(0,-2.255) 36(0,2.255) 37(0.8,-2.255) 38(0.8,2.255) 39(1.6,-2.255) 40(1.6,2.255) 41(2.4,-2.255) 42(2.4,2.255) 43(3.2,-2.255) 44(3.2,2.255) 45(4,-2.255) 46(4,2.255) 47(4.8,-2.255) 48(4.8,2.255) 49(5.6,-2.255) 50(5.6,2.255) 51(6.4,-2.255) 52(6.4,2.255) 53(7.2,-2.255) 54(7.2,2.255) 55(8,-2.255) 56(8,2.255) 57(8.8,-2.255) 58(8.8,2.255) 59(9.6,-2.255) 60(9.6,2.255) 61(10.4,-2.255) 62(10.4,2.255) 63(11.2,-2.255) 64(11.2,2.255) 65(12,-2.255) 66(12,2.255) 67(12.8,-2.255) 68(12.8,2.255) 69(13.6,-2.255) 70(13.6,2.255)
  round 1.397 hole 0.838: G1(-16.9,0) G2(16.9,0)
CON_ATX_20PIN
  rect 1.9x1.9 hole 1.4: 1(-18.9,2.75)
  round 1.9 hole 1.4: 2(-14.7,2.75) 3(-10.5,2.75) 4(-6.3,2.75) 5(-2.1,2.75) 6(2.1,2.75) 7(6.3,2.75) 8(10.5,2.75) 9(14.7,2.75) 10(18.9,2.75) 11(-18.9,-2.75) 12(-14.7,-2.75) 13(-10.5,-2.75) 14(-6.3,-2.75) 15(-2.1,-2.75) 16(2.1,-2.75) 17(6.3,-2.75) 18(10.5,-2.75) 19(14.7,-2.75) 20(18.9,-2.75)
CON_BAT_WBA3B2
  round 1.5 hole 0.9: (-5,1.735) 2(0,-1.735)
  rect 1.5x1.5 hole 0.9: 1(5,1.735)
CON_DDR4_DIMM
  round 2.95 hole 2.45: (-74.6,0) (63.4,0)
  oval 1.7x2.95 hole 1.2x2.45: (0,0)
  round 0.95 hole 0.65: 1(-68.9,-2.7) 2(-68.05,-1.1) 3(-67.2,-2.7) 4(-66.35,-1.1) 5(-65.5,-2.7) 6(-64.65,-1.1) 7(-63.8,-2.7) 8(-62.95,-1.1) 9(-62.1,-2.7) 10(-61.25,-1.1) 11(-60.4,-2.7) 12(-59.55,-1.1) 13(-58.7,-2.7) 14(-57.85,-1.1) 15(-57,-2.7) 16(-56.15,-1.1) 17(-55.3,-2.7) 18(-54.45,-1.1) 19(-53.6,-2.7) 20(-52.75,-1.1) 21(-51.9,-2.7) 22(-51.05,-1.1) 23(-50.2,-2.7) 24(-49.35,-1.1) 25(-48.5,-2.7) 26(-47.65,-1.1) 27(-46.8,-2.7) 28(-45.95,-1.1) 29(-45.1,-2.7) 30(-44.25,-1.1) 31(-43.4,-2.7) 32(-42.55,-1.1) 33(-41.7,-2.7) 34(-40.85,-1.1) 35(-40,-2.7) 36(-39.15,-1.1) 37(-38.3,-2.7) 38(-37.45,-1.1) 39(-36.6,-2.7) 40(-35.75,-1.1) 41(-34.9,-2.7) 42(-34.05,-1.1) 43(-33.2,-2.7) 44(-32.35,-1.1) 45(-31.5,-2.7) 46(-30.65,-1.1) 47(-29.8,-2.7) 48(-28.95,-1.1) 49(-28.1,-2.7) 50(-27.25,-1.1) 51(-26.4,-2.7) 52(-25.55,-1.1) 53(-24.7,-2.7) 54(-23.85,-1.1) 55(-23,-2.7) 56(-22.15,-1.1) 57(-21.3,-2.7) 58(-20.45,-1.1) 59(-19.6,-2.7) 60(-18.75,-1.1) 61(-17.9,-2.7) 62(-17.05,-1.1) 63(-16.2,-2.7) 64(-15.35,-1.1) 65(-14.5,-2.7) 66(-13.65,-1.1) 67(-12.8,-2.7) 68(-11.95,-1.1) 69(-11.1,-2.7) 70(-10.25,-1.1) 71(-9.4,-2.7) 72(-8.55,-1.1) 73(-7.7,-2.7) 74(-6.85,-1.1) 75(-6,-2.7) 76(-5.15,-1.1) 77(-4.3,-2.7) 78(1.65,-1.1) 79(2.5,-2.7) 80(3.35,-1.1) 81(4.2,-2.7) 82(5.05,-1.1) 83(5.9,-2.7) 84(6.75,-1.1) 85(7.6,-2.7) 86(8.45,-1.1) 87(9.3,-2.7) 88(10.15,-1.1) 89(11,-2.7) 90(11.85,-1.1) 91(12.7,-2.7) 92(13.55,-1.1) 93(14.4,-2.7) 94(15.25,-1.1) 95(16.1,-2.7) 96(16.95,-1.1) 97(17.8,-2.7) 98(18.65,-1.1) 99(19.5,-2.7) 100(20.35,-1.1) 101(21.2,-2.7) 102(22.05,-1.1) 103(22.9,-2.7) 104(23.75,-1.1) 105(24.6,-2.7) 106(25.45,-1.1) 107(26.3,-2.7) 108(27.15,-1.1) 109(28,-2.7) 110(28.85,-1.1) 111(29.7,-2.7) 112(30.55,-1.1) 113(31.4,-2.7) 114(32.25,-1.1) 115(33.1,-2.7) 116(33.95,-1.1) 117(34.8,-2.7) 118(35.65,-1.1) 119(36.5,-2.7) 120(37.35,-1.1) 121(38.2,-2.7) 122(39.05,-1.1) 123(39.9,-2.7) 124(40.75,-1.1) 125(41.6,-2.7) 126(42.45,-1.1) 127(43.3,-2.7) 128(44.15,-1.1) 129(45,-2.7) 130(45.85,-1.1) 131(46.7,-2.7) 132(47.55,-1.1) 133(48.4,-2.7) 134(49.25,-1.1) 135(50.1,-2.7) 136(50.95,-1.1) 137(51.8,-2.7) 138(52.65,-1.1) 139(53.5,-2.7) 140(54.35,-1.1) 141(55.2,-2.7) 142(56.05,-1.1) 143(56.9,-2.7) 144(57.75,-1.1) 145(-68.9,1.1) 146(-68.05,2.7) 147(-67.2,1.1) 148(-66.35,2.7) 149(-65.5,1.1) 150(-64.65,2.7) 151(-63.8,1.1) 152(-62.95,2.7) 153(-62.1,1.1) 154(-61.25,2.7) 155(-60.4,1.1) 156(-59.55,2.7) 157(-58.7,1.1) 158(-57.85,2.7) 159(-57,1.1) 160(-56.15,2.7) 161(-55.3,1.1) 162(-54.45,2.7) 163(-53.6,1.1) 164(-52.75,2.7) 165(-51.9,1.1) 166(-51.05,2.7) 167(-50.2,1.1) 168(-49.35,2.7) 169(-48.5,1.1) 170(-47.65,2.7) 171(-46.8,1.1) 172(-45.95,2.7) 173(-45.1,1.1) 174(-44.25,2.7) 175(-43.4,1.1) 176(-42.55,2.7) 177(-41.7,1.1) 178(-40.85,2.7) 179(-40,1.1) 180(-39.15,2.7) 181(-38.3,1.1) 182(-37.45,2.7) 183(-36.6,1.1) 184(-35.75,2.7) 185(-34.9,1.1) 186(-34.05,2.7) 187(-33.2,1.1) 188(-32.35,2.7) 189(-31.5,1.1) 190(-30.65,2.7) 191(-29.8,1.1) 192(-28.95,2.7) 193(-28.1,1.1) 194(-27.25,2.7) 195(-26.4,1.1) 196(-25.55,2.7) 197(-24.7,1.1) 198(-23.85,2.7) 199(-23,1.1) 200(-22.15,2.7) 201(-21.3,1.1) 202(-20.45,2.7) 203(-19.6,1.1) 204(-18.75,2.7) 205(-17.9,1.1) 206(-17.05,2.7) 207(-16.2,1.1) 208(-15.35,2.7) 209(-14.5,1.1) 210(-13.65,2.7) 211(-12.8,1.1) 212(-11.95,2.7) 213(-11.1,1.1) 214(-10.25,2.7) 215(-9.4,1.1) 216(-8.55,2.7) 217(-7.7,1.1) 218(-6.85,2.7) 219(-6,1.1) 220(-5.15,2.7) 221(-4.3,1.1) 222(1.65,2.7) 223(2.5,1.1) 224(3.35,2.7) 225(4.2,1.1) 226(5.05,2.7) 227(5.9,1.1) 228(6.75,2.7) 229(7.6,1.1) 230(8.45,2.7) 231(9.3,1.1) 232(10.15,2.7) 233(11,1.1) 234(11.85,2.7) 235(12.7,1.1) 236(13.55,2.7) 237(14.4,1.1) 238(15.25,2.7) 239(16.1,1.1) 240(16.95,2.7) 241(17.8,1.1) 242(18.65,2.7) 243(19.5,1.1) 244(20.35,2.7) 245(21.2,1.1) 246(22.05,2.7) 247(22.9,1.1) 248(23.75,2.7) 249(24.6,1.1) 250(25.45,2.7) 251(26.3,1.1) 252(27.15,2.7) 253(28,1.1) 254(28.85,2.7) 255(29.7,1.1) 256(30.55,2.7) 257(31.4,1.1) 258(32.25,2.7) 259(33.1,1.1) 260(33.95,2.7) 261(34.8,1.1) 262(35.65,2.7) 263(36.5,1.1) 264(37.35,2.7) 265(38.2,1.1) 266(39.05,2.7) 267(39.9,1.1) 268(40.75,2.7) 269(41.6,1.1) 270(42.45,2.7) 271(43.3,1.1) 272(44.15,2.7) 273(45,1.1) 274(45.85,2.7) 275(46.7,1.1) 276(47.55,2.7) 277(48.4,1.1) 278(49.25,2.7) 279(50.1,1.1) 280(50.95,2.7) 281(51.8,1.1) 282(52.65,2.7) 283(53.5,1.1) 284(54.35,2.7) 285(55.2,1.1) 286(56.05,2.7) 287(56.9,1.1) 288(57.75,2.7)
CON_FPC_DF14_20P
  round 1.1 hole 1.1 unplated: (-14.475,5.1) (14.475,5.1)
  rect 0.7x1.8 smd: 1(-11.875,6.2) 2(-10.625,6.2) 3(-9.375,6.2) 4(-8.125,6.2) 5(-6.875,6.2) 6(-5.625,6.2) 7(-4.375,6.2) 8(-3.125,6.2) 9(-1.875,6.2) 10(-0.625,6.2) 11(0.625,6.2) 12(1.875,6.2) 13(3.125,6.2) 14(4.375,6.2) 15(5.625,6.2) 16(6.875,6.2) 17(8.125,6.2) 18(9.375,6.2) 19(10.625,6.2) 20(11.875,6.2)
  rect 2x2.6 smd: 21(-14.275,1.1) 22(14.275,1.1)
CON_HDMI
  rect 0.3x2.6 smd: 1(4.5,10.31) 2(4,10.31) 3(3.5,10.31) 4(3,10.31) 5(2.5,10.31) 6(2,10.31) 7(1.5,10.31) 8(1,10.31) 9(0.5,10.31) 10(0,10.31) 11(-0.5,10.31) 12(-1,10.31) 13(-1.5,10.31) 14(-2,10.31) 15(-2.5,10.31) 16(-3,10.31) 17(-3.5,10.31) 18(-4,10.31) 19(-4.5,10.31)
  oval 1.5x3.3 hole 0.9: 20(-7.25,9.55) 21(7.25,9.55)
  oval 1.5x2.3 hole 0.9: 22(-7.25,3.59) 23(7.25,3.59)
CON_MEC6_120
  round 1.55 hole 1.55 unplated: (-1.5,7.535) (0,-7.535)
  rect 1.8x0.4 smd: 1(3.85,6.033) 2(-3.85,6.033) 3(3.85,5.398) 4(-3.85,5.398) 5(3.85,4.763) 6(-3.85,4.763) 7(3.85,4.128) 8(-3.85,4.128) 9(3.85,3.493) 10(-3.85,3.493) 11(3.85,2.858) 12(-3.85,2.858) 13(3.85,2.223) 14(-3.85,2.223) 15(3.85,1.588) 16(-3.85,1.588) 17(3.85,0.953) 18(-3.85,0.953) 19(3.85,0.318) 20(-3.85,0.318) 21(3.85,-0.317) 22(-3.85,-0.317) 23(3.85,-0.952) 24(-3.85,-0.952) 25(3.85,-1.587) 26(-3.85,-1.587) 27(3.85,-2.222) 28(-3.85,-2.222) 29(3.85,-2.857) 30(-3.85,-2.857) 31(3.85,-3.492) 32(-3.85,-3.492) 33(3.85,-4.127) 34(-3.85,-4.127) 35(3.85,-4.762) 36(-3.85,-4.762) 37(3.85,-5.397) 38(-3.85,-5.397) 39(3.85,-6.032) 40(-3.85,-6.032)
CON_MINIPCIE
  round 1.1 hole 1.1 unplated: (-12.5,0)
  round 1.6 hole 1.6 unplated: (12.5,0)
  rect 0.6x2 smd: 1(11.8,4.1) 2(11.4,-4.1) 3(11,4.1) 4(10.6,-4.1) 5(10.2,4.1) 6(9.8,-4.1) 7(9.4,4.1) 8(9,-4.1) 9(8.6,4.1) 10(8.2,-4.1) 11(7.8,4.1) 12(7.4,-4.1) 13(7,4.1) 14(6.6,-4.1) 15(6.2,4.1) 16(5.8,-4.1) 17(2.2,4.1) 18(1.8,-4.1) 19(1.4,4.1) 20(1,-4.1) 21(0.6,4.1) 22(0.2,-4.1) 23(-0.2,4.1) 24(-0.6,-4.1) 25(-1,4.1) 26(-1.4,-4.1) 27(-1.8,4.1) 28(-2.2,-4.1) 29(-2.6,4.1) 30(-3,-4.1) 31(-3.4,4.1) 32(-3.8,-4.1) 33(-4.2,4.1) 34(-4.6,-4.1) 35(-5,4.1) 36(-5.4,-4.1) 37(-5.8,4.1) 38(-6.2,-4.1) 39(-6.6,4.1) 40(-7,-4.1) 41(-7.4,4.1) 42(-7.8,-4.1) 43(-8.2,4.1) 44(-8.6,-4.1) 45(-9,4.1) 46(-9.4,-4.1) 47(-9.8,4.1) 48(-10.2,-4.1) 49(-10.6,4.1) 50(-11,-4.1) 51(-11.4,4.1) 52(-11.8,-4.1)
  rect 2.3x3.2 smd: 53(14.65,3.5) 54(-14.65,3.5)
CON_PEX1
  round 2.35 hole 2.35 unplated: (0,0) (9.15,0)
  rect 1.1x1.1 hole 0.7: A1(-11.65,1.25)
  round 1.1 hole 0.7: A2(-10.65,3.25) A3(-9.65,1.25) A4(-8.65,3.25) A5(-7.65,1.25) A6(-6.65,3.25) A7(-5.65,1.25) A8(-4.65,3.25) A9(-3.65,1.25) A10(-2.65,3.25) A11(-1.65,1.25) A12(1.35,3.25) A13(2.35,1.25) A14(3.35,3.25) A15(4.35,1.25) A16(5.35,3.25) A17(6.35,1.25) A18(7.35,3.25) B1(-11.65,-1.25) B2(-10.65,-3.25) B3(-9.65,-1.25) B4(-8.65,-3.25) B5(-7.65,-1.25) B6(-6.65,-3.25) B7(-5.65,-1.25) B8(-4.65,-3.25) B9(-3.65,-1.25) B10(-2.65,-3.25) B11(-1.65,-1.25) B12(1.35,-3.25) B13(2.35,-1.25) B14(3.35,-3.25) B15(4.35,-1.25) B16(5.35,-3.25) B17(6.35,-1.25) B18(7.35,-3.25)
CON_RJ45_2X1_LED
  round 3.2 hole 3.2 unplated: (-6.35,5.46) (6.35,5.46)
  round 2.2 hole 1.6: 25(-8.13,12.57) 26(8.13,12.57) 27(-8.13,20.95) 28(8.13,20.95)
  round 1.4 hole 0.9: A1(4.445,22.48) A2(3.175,19.94) A3(1.905,22.48) A4(0.635,19.94) A5(-0.635,22.48) A6(-1.905,19.94) A7(-3.175,22.48) A8(-4.445,19.94) B1(-4.445,13.71) B2(-3.175,16.25) B3(-1.905,13.71) B4(-0.635,16.25) B5(0.635,13.71) B6(1.905,16.25) B7(3.175,13.71) B8(4.445,16.25)
  round 1.6 hole 1.1: A9(-6.86,26.41) A10(-4.32,26.41) A11(4.32,26.41) A12(6.86,26.41) B9(-6.86,9.65) B10(-4.32,9.65) B11(4.32,9.65) B12(6.86,9.65)
CON_RJ45_2X4_LED
  round 3.2 hole 3.2 unplated: (-29.975,5.46) (29.975,5.46)
  round 2.2 hole 1.6: 97(-31.755,12.57) 98(31.755,12.57) 99(-31.755,20.95) 100(31.755,20.95)
  round 1.4 hole 0.9: A1(-19.18,22.48) A2(-20.45,19.94) A3(-21.72,22.48) A4(-22.99,19.94) A5(-24.26,22.48) A6(-25.53,19.94) A7(-26.8,22.48) A8(-28.07,19.94) B1(-28.07,13.71) B2(-26.8,16.25) B3(-25.53,13.71) B4(-24.26,16.25) B5(-22.99,13.71) B6(-21.72,16.25) B7(-20.45,13.71) B8(-19.18,16.25) C1(-3.43,22.48) C2(-4.7,19.94) C3(-5.97,22.48) C4(-7.24,19.94) C5(-8.51,22.48) C6(-9.78,19.94) C7(-11.05,22.48) C8(-12.32,19.94) D1(-12.32,13.71) D2(-11.05,16.25) D3(-9.78,13.71) D4(-8.51,16.25) D5(-7.24,13.71) D6(-5.97,16.25) D7(-4.7,13.71) D8(-3.43,16.25) E1(12.32,22.48) E2(11.05,19.94) E3(9.78,22.48) E4(8.51,19.94) E5(7.24,22.48) E6(5.97,19.94) E7(4.7,22.48) E8(3.43,19.94) F1(3.43,13.71) F2(4.7,16.25) F3(5.97,13.71) F4(7.24,16.25) F5(8.51,13.71) F6(9.78,16.25) F7(11.05,13.71) F8(12.32,16.25) G1(28.07,22.48) G2(26.8,19.94) G3(25.53,22.48) G4(24.26,19.94) G5(22.99,22.48) G6(21.72,19.94) G7(20.45,22.48) G8(19.18,19.94) H1(19.18,13.71) H2(20.45,16.25) H3(21.72,13.71) H4(22.99,16.25) H5(24.26,13.71) H6(25.53,16.25) H7(26.8,13.71) H8(28.07,16.25)
  round 1.6 hole 1.1: A9(-30.485,26.41) A10(-27.945,26.41) A11(-19.305,26.41) A12(-16.765,26.41) B9(-30.485,9.65) B10(-27.945,9.65) B11(-19.305,9.65) B12(-16.765,9.65) C9(-14.735,26.41) C10(-12.195,26.41) C11(-3.555,26.41) C12(-1.015,26.41) D9(-14.735,9.65) D10(-12.195,9.65) D11(-3.555,9.65) D12(-1.015,9.65) E9(1.015,26.41) E10(3.555,26.41) E11(12.195,26.41) E12(14.735,26.41) F9(1.015,9.65) F10(3.555,9.65) F11(12.195,9.65) F12(14.735,9.65) G9(16.765,26.41) G10(19.305,26.41) G11(27.945,26.41) G12(30.485,26.41) H9(16.765,9.65) H10(19.305,9.65) H11(27.945,9.65) H12(30.485,9.65)
CON_RJ45_UP_1X1_LED
  round 3.25 hole 3.25 unplated: (-6.35,5.48) (6.35,5.48)
  round 1.3 hole 0.9: 1(3.57,8.02) 2(2.55,9.8) 3(1.53,8.02) 4(0.51,9.8) 5(-0.51,8.02) 6(-1.53,9.8) 7(-2.55,8.02) 8(-3.57,9.8)
  round 1.5 hole 0.9: 9(-6.86,14.62) 10(-4.57,14.62) 11(4.57,14.62) 12(6.86,14.62)
  round 2.2 hole 1.6: 13(-8.13,8.91) 14(8.13,8.91)
CON_SATA
  round 1.1 hole 0.74: 1(-3.81,1.5) 2(-2.54,0) 3(-1.27,0) 4(0,1.5) 5(1.27,0) 6(2.54,0) 7(3.81,1.5)
  round 1.85 hole 1.35: 8(-6.27,0) 9(6.56,-1)
CON_SD
  round 1.5 hole 1.5 unplated: (-12.1,5.5) (12.1,5.5)
  rect 0.8x2 smd: 1(-6.88,30) 2(-4.38,30) 3(-1.05,30) 4(0.62,30) 5(3.12,30) 6(5.62,30) 7(8.05,30) 8(9.75,30) 9(-9.38,30) 10(-2.71,30)
  rect 0.7x2 smd: 11(13.24,30)
  rect 1.8x2.4 smd: 12(-14.1,8.8)
  rect 1.7x2.4 smd: 13(13.25,7.6)
CON_SW_60X60_2P2_34
  round 1.5 hole 1: 1(-2.25,2.45) 2(2.25,2.45)
  round 1.8 hole 1.3: 3(-3.5,4.95) 4(3.5,4.95)
CON_SWITCH_X8
  rect 1.27x0.76 smd: 1(-3.81,4.445) 2(-3.81,3.175) 3(-3.81,1.905) 4(-3.81,0.635) 5(-3.81,-0.635) 6(-3.81,-1.905) 7(-3.81,-3.175) 8(-3.81,-4.445) 9(3.81,-4.445) 10(3.81,-3.175) 11(3.81,-1.905) 12(3.81,-0.635) 13(3.81,0.635) 14(3.81,1.905) 15(3.81,3.175) 16(3.81,4.445)
CON_USB_A_2
  round 1.4 hole 0.9: 1(-3.5,15.61) 2(-1,15.61) 3(1,15.61) 4(3.5,15.61) 5(-3.5,12.99) 6(-1,12.99) 7(1,12.99) 8(3.5,12.99)
  round 3.3 hole 2.3: 9(-6.57,10.28) 10(6.57,10.28) 11(-6.57,15.96) 12(6.57,15.96)
CON_WAFER_P254_S_1X3
  round 1.5 hole 1: 1(2.54,0) 2(0,0) 3(-2.54,0)
CRY_32X25_4
  rect 1.4x1.2 smd: 1(-1.1,-0.85) 2(1.1,-0.85) 3(1.1,0.85) 4(-1.1,0.85)
CRY_69X14_4
  rect 1.2x0.6 smd: 1(-3.15,-0.45) 2(3.15,-0.45) 3(3.15,0.45) 4(-3.15,0.45)
DFN_P050_D040_B300_10_E230X150
  custom 0.07x0.07 smd: 1(-1.5,1) 2(-1.5,0.5) 3(-1.5,0) 4(-1.5,-0.5) 5(-1.5,-1) 6(1.5,-1) 7(1.5,-0.5) 8(1.5,0) 9(1.5,0.5) 10(1.5,1)
  rect 1.5x2.3 smd: 11(0,0)
DFN_P050_D040_B300_10_E240X165
  custom 0.07x0.07 smd: 1(-1.5,1) 2(-1.5,0.5) 3(-1.5,0) 4(-1.5,-0.5) 5(-1.5,-1) 6(1.5,-1) 7(1.5,-0.5) 8(1.5,0) 9(1.5,0.5) 10(1.5,1)
  custom 0.412x0.412 smd: 11(0,0)
DUALDB-9MM
  rect 2.007x2.007 hole 1.194: 1(0,0) 11(0,-6.581)
  round 2.007 hole 1.194: 2(2.769,0) 3(5.537,0) 4(8.306,0) 5(11.074,0) 6(1.384,-2.84) 7(4.153,-2.84) 8(6.921,-2.84) 9(9.69,-2.84) 12(2.769,-6.581) 13(5.537,-6.581) 14(8.306,-6.581) 15(11.074,-6.581) 16(1.384,-9.421) 17(4.153,-9.421) 18(6.921,-9.421) 19(9.69,-9.421)
  round 5.055 hole 3.048: 10(18.031,-1.42) 20(18.031,-9.421) 21(-6.957,-9.421) 22(-6.957,-1.42)
FIDUCIAL
  round 1 smd: 1(0,0)
HDR_P254_HTST_2X8
  rect 5.08x1.27 smd: 1(-3.43,0) 2(3.43,0) 3(-3.43,-2.54) 4(3.43,-2.54) 5(-3.43,-5.08) 6(3.43,-5.08) 7(-3.43,-7.62) 8(3.43,-7.62) 9(-3.43,-10.16) 10(3.43,-10.16) 11(-3.43,-12.7) 12(3.43,-12.7) 13(-3.43,-15.24) 14(3.43,-15.24) 15(-3.43,-17.78) 16(3.43,-17.78)
HDR_P254_M_T_1X5
  rect 1.5x1.5 hole 1: 1(0,0)
  round 1.5 hole 1: 2(0,-2.54) 3(0,-5.08) 4(0,-7.62) 5(0,-10.16)
HDR_P254_M_T_2X5
  rect 1.5x1.5 hole 1: 1(-1.27,0)
  round 1.5 hole 1: 2(1.27,0) 3(-1.27,-2.54) 4(1.27,-2.54) 5(-1.27,-5.08) 6(1.27,-5.08) 7(-1.27,-7.62) 8(1.27,-7.62) 9(-1.27,-10.16) 10(1.27,-10.16)
IND_CM_2012
  rect 0.9x0.4 smd: 1(-0.85,-0.35) 2(0.85,-0.35) 3(0.85,0.35) 4(-0.85,0.35)
IND_IHLP_2525
  rect 1.83x3.43 smd: 1(-2.77,0) 2(2.77,0)
IND_IHLP_4040
  rect 3.5x4.95 smd: 1(-4.75,0) 2(4.75,0)
IND_SWPA2520
  rect 0.85x2 smd: 1(-0.825,0) 2(0.825,0)
JMP_P254_T_1X2
  round 1.5 hole 1: 1(0,0) 2(0,-2.54)
JMP_P254_T_1X3
  round 1.5 hole 1: 1(0,0) 2(0,-2.54) 3(0,-5.08)
LED_0603
  rect 0.9x0.9 smd: 1(-0.8,0) 2(0.8,0)
LED_PM_1S
  rect 1.5x3.5 smd: 1(1.27,5.25) 2(-1.27,5.25)
MAG_H5008
  rect 0.64x1.9 smd: 1(-5.45,-8.83) 2(-4.46,-8.83) 3(-3.47,-8.83) 4(-2.48,-8.83) 5(-1.49,-8.83) 6(-0.5,-8.83) 7(0.49,-8.83) 8(1.48,-8.83) 9(2.47,-8.83) 10(3.46,-8.83) 11(4.45,-8.83) 12(5.44,-8.83) 13(5.45,8.83) 14(4.46,8.83) 15(3.47,8.83) 16(2.48,8.83) 17(1.49,8.83) 18(0.5,8.83) 19(-0.49,8.83) 20(-1.48,8.83) 21(-2.47,8.83) 22(-3.46,8.83) 23(-4.45,8.83) 24(-5.44,8.83)
MH_580S340P
  rect 5.8x5.8 hole 3.4: 1(0,0)
MH_680C320P
  round 6.8 hole 3.2: 1(0,0)
MH_900C400N_M
  round 4 hole 4 unplated: (0,0)
  round 1 hole 0.5: 1(0,3) 2(-2.121,2.121) 3(-3,0) 4(-2.121,-2.121) 5(0,-3) 6(2.121,-2.121) 7(3,0) 8(2.121,2.121)
MSOP_8
  rect 1.5x0.35 smd: 1(-2.2,0.975) 2(-2.2,0.325) 3(-2.2,-0.325) 4(-2.2,-0.975) 5(2.2,-0.975) 6(2.2,-0.325) 7(2.2,0.325) 8(2.2,0.975)
MSOP_8_E170
  rect 1.5x0.35 smd: 1(-2.2,0.975) 2(-2.2,0.325) 3(-2.2,-0.325) 4(-2.2,-0.975) 5(2.2,-0.975) 6(2.2,-0.325) 7(2.2,0.325) 8(2.2,0.975)
  rect 1.7x1.7 smd: 9(0,0)
MSOP_10
  rect 1.5x0.28 smd: 1(-2.2,1) 2(-2.2,0.5) 3(-2.2,0) 4(-2.2,-0.5) 5(-2.2,-1) 6(2.2,-1) 7(2.2,-0.5) 8(2.2,0) 9(2.2,0.5) 10(2.2,1)
NFM21
  rect 0.8x1.4 smd: 1(-1,0) 2(1,0)
  rect 0.7x0.7 smd: 3(0,0.625) 4(0,-0.625)
OSC_7X5_4
  rect 1.8x2 smd: 1(-2.54,-2.1) 2(2.54,-2.1) 3(2.54,2.1) 4(-2.54,2.1)
OSC_32X25_4
  rect 1.4x1.2 smd: 1(-1.1,-0.85) 2(1.1,-0.85) 3(1.1,0.85) 4(-1.1,0.85)
QFN_P040_D040_B500_40_E370
  custom 0.05x0.05 smd: 1(-2.5,1.8) 2(-2.5,1.4) 3(-2.5,1) 4(-2.5,0.6) 5(-2.5,0.2) 6(-2.5,-0.2) 7(-2.5,-0.6) 8(-2.5,-1) 9(-2.5,-1.4) 10(-2.5,-1.8) 11(-1.8,-2.5) 12(-1.4,-2.5) 13(-1,-2.5) 14(-0.6,-2.5) 15(-0.2,-2.5) 16(0.2,-2.5) 17(0.6,-2.5) 18(1,-2.5) 19(1.4,-2.5) 20(1.8,-2.5) 21(2.5,-1.8) 22(2.5,-1.4) 23(2.5,-1) 24(2.5,-0.6) 25(2.5,-0.2) 26(2.5,0.2) 27(2.5,0.6) 28(2.5,1) 29(2.5,1.4) 30(2.5,1.8) 31(1.8,2.5) 32(1.4,2.5) 33(1,2.5) 34(0.6,2.5) 35(0.2,2.5) 36(-0.2,2.5) 37(-0.6,2.5) 38(-1,2.5) 39(-1.4,2.5) 40(-1.8,2.5)
  rect 3.7x3.7 smd: 41(0,0)
QFN_P040_D040_B600_48_E440
  custom 0.05x0.05 smd: 1(-3,2.2) 2(-3,1.8) 3(-3,1.4) 4(-3,1) 5(-3,0.6) 6(-3,0.2) 7(-3,-0.2) 8(-3,-0.6) 9(-3,-1) 10(-3,-1.4) 11(-3,-1.8) 12(-3,-2.2) 13(-2.2,-3) 14(-1.8,-3) 15(-1.4,-3) 16(-1,-3) 17(-0.6,-3) 18(-0.2,-3) 19(0.2,-3) 20(0.6,-3) 21(1,-3) 22(1.4,-3) 23(1.8,-3) 24(2.2,-3) 25(3,-2.2) 26(3,-1.8) 27(3,-1.4) 28(3,-1) 29(3,-0.6) 30(3,-0.2) 31(3,0.2) 32(3,0.6) 33(3,1) 34(3,1.4) 35(3,1.8) 36(3,2.2) 37(2.2,3) 38(1.8,3) 39(1.4,3) 40(1,3) 41(0.6,3) 42(0.2,3) 43(-0.2,3) 44(-0.6,3) 45(-1,3) 46(-1.4,3) 47(-1.8,3) 48(-2.2,3)
  rect 4.4x4.4 smd: 49(0,0)
QFN_P040_D040_B1000_88_E600
  custom 0.05x0.05 smd: 1(-5,4.2) 2(-5,3.8) 3(-5,3.4) 4(-5,3) 5(-5,2.6) 6(-5,2.2) 7(-5,1.8) 8(-5,1.4) 9(-5,1) 10(-5,0.6) 11(-5,0.2) 12(-5,-0.2) 13(-5,-0.6) 14(-5,-1) 15(-5,-1.4) 16(-5,-1.8) 17(-5,-2.2) 18(-5,-2.6) 19(-5,-3) 20(-5,-3.4) 21(-5,-3.8) 22(-5,-4.2) 23(-4.2,-5) 24(-3.8,-5) 25(-3.4,-5) 26(-3,-5) 27(-2.6,-5) 28(-2.2,-5) 29(-1.8,-5) 30(-1.4,-5) 31(-1,-5) 32(-0.6,-5) 33(-0.2,-5) 34(0.2,-5) 35(0.6,-5) 36(1,-5) 37(1.4,-5) 38(1.8,-5) 39(2.2,-5) 40(2.6,-5) 41(3,-5) 42(3.4,-5) 43(3.8,-5) 44(4.2,-5) 45(5,-4.2) 46(5,-3.8) 47(5,-3.4) 48(5,-3) 49(5,-2.6) 50(5,-2.2) 51(5,-1.8) 52(5,-1.4) 53(5,-1) 54(5,-0.6) 55(5,-0.2) 56(5,0.2) 57(5,0.6) 58(5,1) 59(5,1.4) 60(5,1.8) 61(5,2.2) 62(5,2.6) 63(5,3) 64(5,3.4) 65(5,3.8) 66(5,4.2) 67(4.2,5) 68(3.8,5) 69(3.4,5) 70(3,5) 71(2.6,5) 72(2.2,5) 73(1.8,5) 74(1.4,5) 75(1,5) 76(0.6,5) 77(0.2,5) 78(-0.2,5) 79(-0.6,5) 80(-1,5) 81(-1.4,5) 82(-1.8,5) 83(-2.2,5) 84(-2.6,5) 85(-3,5) 86(-3.4,5) 87(-3.8,5) 88(-4.2,5)
  rect 6x6 smd: 89(0,0)
QFN_P050_D040_B450X250_20_E3X1
  custom 0.07x0.07 smd: 1(-0.25,2.25) 2(-1.25,1.75) 3(-1.25,1.25) 4(-1.25,0.75) 5(-1.25,0.25) 6(-1.25,-0.25) 7(-1.25,-0.75) 8(-1.25,-1.25) 9(-1.25,-1.75) 10(-0.25,-2.25) 11(0.25,-2.25) 12(1.25,-1.75) 13(1.25,-1.25) 14(1.25,-0.75) 15(1.25,-0.25) 16(1.25,0.25) 17(1.25,0.75) 18(1.25,1.25) 19(1.25,1.75) 20(0.25,2.25)
  rect 1x3 smd: 21(0,0)
QFN_SUPIRBUCK_4X5
  custom 0.07x0.07 smd: 1(-1.5,-2.5) 2(-1,-2.5) 3(-0.5,-2.5) 4(0,-2.5) 5(0.5,-2.5) 6(1,-2.5) 7(1.5,-2.5) 8(2,-1.65) 9(2,-1.15) 10(2,-0.65) 14(-2,-0.65) 15(-2,-1.15) 16(-2,-1.65)
  rect 0.92x2.07 smd: 11(1.9,1.205)
  rect 1.74x2.94 smd: 12(0.29,1.39)
  rect 1.49x2.07 smd: 13(-1.615,1.205)
  custom 0.33x0.33 smd: 17(0,-1.15)
QFN_VSC8514
  rect 4.8x4.8 smd: 139(0.325,-0.65)
  round 0.76 smd: A1(-5.45,5.45) A4(-5.45,-5.45) A5(5.45,-5.45) A6(5.45,5.45)
  round 0.35 smd: A2(-5.626,-1.3) A3(-5.626,-1.95) A8(0.325,5.301) A9(-0.325,5.301) B1(-4.976,1.625) B2(-4.976,0.975) B3(-4.976,-0.325) B4(-4.976,-0.975) B5(-4.976,-1.625) B6(-4.976,-2.925) B8(-4.976,-4.225) B9(5.626,-3.575) B10(5.626,-2.925) B11(5.627,-0.975) B12(5.627,-0.325) B15(2.6,4.651) B16(1.95,4.651) B17(1.3,4.651) B20(-1.3,4.651) C1(-4.326,3.25) C2(-4.326,1.95) C4(-4.326,0.65) C5(-4.326,0) C6(-4.326,-1.3) C7(-4.326,-1.95) C8(-4.326,-2.6) C9(-4.326,-3.25) C10(-4.327,-4.55) C11(-4.225,-5.302) C12(-2.275,-5.302) C13(-1.625,-5.302) C14(4.976,-4.55) C15(4.976,-3.9) C16(4.976,-3.25) C17(4.976,-2.6) C18(4.976,-1.3) C19(4.976,-0.65) C20(4.976,0.65) C21(4.976,1.95) C22(4.976,2.6) C23(4.976,3.25) C24(4.225,4.001) C25(3.575,4.001) C26(2.925,4.001) C27(2.275,4.001) C30(0.325,4.001) C34(-2.275,4.001) C35(-2.925,4.001) C36(-4.225,4.001) D1(-3.676,2.275) D2(-3.676,1.625) D3(-3.676,0.975) D4(-3.676,0.325) D5(-3.676,-0.325) D6(-3.676,-0.975) D7(-3.676,-1.625) D10(-3.676,-4.225) D11(-2.6,-4.652) D12(-1.95,-4.652) D13(-0.65,-4.652) D14(0,-4.652) D15(1.3,-4.652) D16(1.95,-4.652) D17(2.6,-4.652) D18(3.25,-4.652) D19(4.327,-4.225) D20(4.327,-3.575) D22(4.327,-2.275) D23(4.327,-1.625) D24(4.327,-0.975) D25(4.327,-0.325) D26(4.327,0.325) D28(4.327,1.625) D29(3.9,3.351) D31(2.6,3.351) D32(-1.3,3.351) D34(-2.6,3.351) E1(-3.027,2.6) E2(-3.027,1.3) E5(-3.026,-0.65) E6(-3.026,-1.3) E7(-3.026,-1.95) E8(-3.026,-2.6) E9(-3.026,-3.25) E10(-2.925,-4.002) E12(-1.625,-4.002) E13(-0.975,-4.002) E15(0.325,-4.002) E17(1.625,-4.002) E19(3.575,-4.002) E21(3.676,-2.6) E22(3.676,-1.95) E23(3.676,-1.3) E24(3.676,-0.65) E25(3.676,0) E27(3.676,1.3) E28(3.676,1.95) E29(2.925,2.702) E30(2.275,2.702) E31(1.625,2.702) E32(0.975,2.702) E33(0.325,2.702) E34(-0.325,2.702) E35(-0.975,2.702) E36(-1.625,2.702) E37(-2.275,2.702)
  oval 0.5x0.35 smd: A7(0.975,5.301) A10(-0.975,5.301) B19(-0.65,4.651) C28(1.625,4.001) C29(0.975,4.001) C31(-0.325,4.001) C32(-0.975,4.001) C33(-1.625,4.001) D35(-3.25,3.351) E11(-2.275,-4.002) E14(-0.325,-4.002) E16(0.975,-4.002)
  oval 0.35x0.5 smd: B7(-4.976,-3.575) C3(-4.326,1.3) D8(-3.676,-2.275) D9(-3.676,-2.925) D21(4.327,-2.925) E3(-3.027,0.65) E4(-3.027,0) E20(3.676,-3.25)
  oval 0.35x0.65 smd: B13(5.627,0.975) B14(5.627,2.275) D27(4.327,0.975) E26(3.676,0.65)
  oval 0.65x0.35 smd: B18(0.65,4.651) D30(3.25,3.351) D33(-1.95,3.351) E18(2.275,-4.002)
QFP_P050_64
  rect 1.5x0.28 smd: 1(-5.75,3.75) 2(-5.75,3.25) 3(-5.75,2.75) 4(-5.75,2.25) 5(-5.75,1.75) 6(-5.75,1.25) 7(-5.75,0.75) 8(-5.75,0.25) 9(-5.75,-0.25) 10(-5.75,-0.75) 11(-5.75,-1.25) 12(-5.75,-1.75) 13(-5.75,-2.25) 14(-5.75,-2.75) 15(-5.75,-3.25) 16(-5.75,-3.75) 33(5.75,-3.75) 34(5.75,-3.25) 35(5.75,-2.75) 36(5.75,-2.25) 37(5.75,-1.75) 38(5.75,-1.25) 39(5.75,-0.75) 40(5.75,-0.25) 41(5.75,0.25) 42(5.75,0.75) 43(5.75,1.25) 44(5.75,1.75) 45(5.75,2.25) 46(5.75,2.75) 47(5.75,3.25) 48(5.75,3.75)
  rect 0.28x1.5 smd: 17(-3.75,-5.76) 18(-3.25,-5.76) 19(-2.75,-5.76) 20(-2.25,-5.76) 21(-1.75,-5.76) 22(-1.25,-5.76) 23(-0.75,-5.76) 24(-0.25,-5.76) 25(0.25,-5.76) 26(0.75,-5.76) 27(1.25,-5.76) 28(1.75,-5.76) 29(2.25,-5.76) 30(2.75,-5.76) 31(3.25,-5.76) 32(3.75,-5.76) 49(3.75,5.75) 50(3.25,5.75) 51(2.75,5.75) 52(2.25,5.75) 53(1.75,5.75) 54(1.25,5.75) 55(0.75,5.75) 56(0.25,5.75) 57(-0.25,5.75) 58(-0.75,5.75) 59(-1.25,5.75) 60(-1.75,5.75) 61(-2.25,5.75) 62(-2.75,5.75) 63(-3.25,5.75) 64(-3.75,5.75)
QFP_P050_100
  rect 1.5x0.28 smd: 1(-7.75,6) 2(-7.75,5.5) 3(-7.75,5) 4(-7.75,4.5) 5(-7.75,4) 6(-7.75,3.5) 7(-7.75,3) 8(-7.75,2.5) 9(-7.75,2) 10(-7.75,1.5) 11(-7.75,1) 12(-7.75,0.5) 13(-7.75,0) 14(-7.75,-0.5) 15(-7.75,-1) 16(-7.75,-1.5) 17(-7.75,-2) 18(-7.75,-2.5) 19(-7.75,-3) 20(-7.75,-3.5) 21(-7.75,-4) 22(-7.75,-4.5) 23(-7.75,-5) 24(-7.75,-5.5) 25(-7.75,-6) 51(7.75,-6) 52(7.75,-5.5) 53(7.75,-5) 54(7.75,-4.5) 55(7.75,-4) 56(7.75,-3.5) 57(7.75,-3) 58(7.75,-2.5) 59(7.75,-2) 60(7.75,-1.5) 61(7.75,-1) 62(7.75,-0.5) 63(7.75,0) 64(7.75,0.5) 65(7.75,1) 66(7.75,1.5) 67(7.75,2) 68(7.75,2.5) 69(7.75,3) 70(7.75,3.5) 71(7.75,4) 72(7.75,4.5) 73(7.75,5) 74(7.75,5.5) 75(7.75,6)
  rect 0.28x1.5 smd: 26(-6,-7.75) 27(-5.5,-7.75) 28(-5,-7.75) 29(-4.5,-7.75) 30(-4,-7.75) 31(-3.5,-7.75) 32(-3,-7.75) 33(-2.5,-7.75) 34(-2,-7.75) 35(-1.5,-7.75) 36(-1,-7.75) 37(-0.5,-7.75) 38(0,-7.75) 39(0.5,-7.75) 40(1,-7.75) 41(1.5,-7.75) 42(2,-7.75) 43(2.5,-7.75) 44(3,-7.75) 45(3.5,-7.75) 46(4,-7.75) 47(4.5,-7.75) 48(5,-7.75) 49(5.5,-7.75) 50(6,-7.75) 76(6,7.75) 77(5.5,7.75) 78(5,7.75) 79(4.5,7.75) 80(4,7.75) 81(3.5,7.75) 82(3,7.75) 83(2.5,7.75) 84(2,7.75) 85(1.5,7.75) 86(1,7.75) 87(0.5,7.75) 88(0,7.75) 89(-0.5,7.75) 90(-1,7.75) 91(-1.5,7.75) 92(-2,7.75) 93(-2.5,7.75) 94(-3,7.75) 95(-3.5,7.75) 96(-4,7.75) 97(-4.5,7.75) 98(-5,7.75) 99(-5.5,7.75) 100(-6,7.75)
RES_WSL2726
  rect 2.44x5.6 smd: 1(-2.48,1.14) 4(2.48,1.14)
  rect 2.44x0.89 smd: 2(-2.48,-2.995) 3(2.48,-2.995)
SC70_5
  rect 0.4x0.8 smd: 1(-0.65,-0.95) 2(0,-0.95) 3(0.65,-0.95) 4(0.65,0.95) 5(-0.65,0.95)
SIP4_2P54_11X6
  rect 1.6x1.6 hole 1.143: 1(0,-0.559)
  round 1.6 hole 1.143: 2(0,-3.099) 3(0,-5.639) 4(0,-8.179)
SO_8
  rect 1.7x0.6 smd: 1(-2.65,1.905) 2(-2.65,0.635) 3(-2.65,-0.635) 4(-2.65,-1.905) 5(2.65,-1.905) 6(2.65,-0.635) 7(2.65,0.635) 8(2.65,1.905)
SO_8_FL
  rect 0.75x1 smd: 1(-1.905,-2.795) 2(-0.635,-2.795) 3(0.635,-2.795) 4(1.905,-2.795)
  custom 1.132x1.132 smd: 5(0,0)
SO_16
  rect 1.7x0.6 smd: 1(-2.65,4.445) 2(-2.65,3.175) 3(-2.65,1.905) 4(-2.65,0.635) 5(-2.65,-0.635) 6(-2.65,-1.905) 7(-2.65,-3.175) 8(-2.65,-4.445) 9(2.65,-4.445) 10(2.65,-3.175) 11(2.65,-1.905) 12(2.65,-0.635) 13(2.65,0.635) 14(2.65,1.905) 15(2.65,3.175) 16(2.65,4.445)
